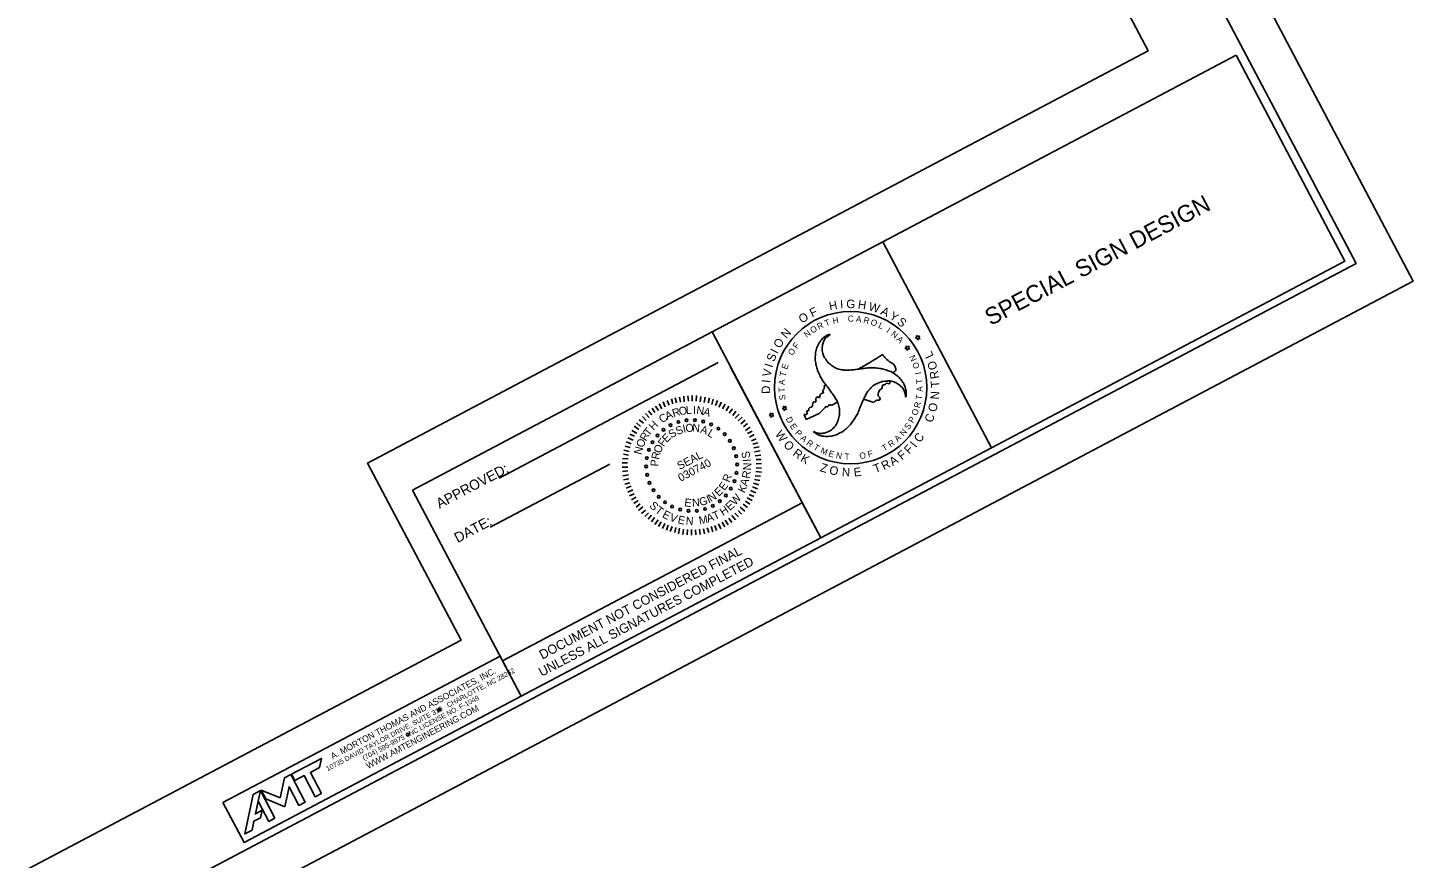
# Model space of a CAD drawing. Extents: x 1789 to 1487599, y -706 to 498569.
# Drawn here: x 2978 to 3796, y -258 to 232 of the extents above; entities that cross this region are included whole.
import ezdxf

# ---------------------------------------------------------------- set-up
doc = ezdxf.new("R2010")
doc.units = 0
for name, color, linetype in [('DEV BORDER CELL', 7, 'Continuous'), ('DEV DOT SWIRL SEAL CELL', 7, 'Continuous'), ('Old_Level_9', 7, 'Continuous'), ('Prop Grid Mask', 7, 'Continuous'), ('Scratch_Level_0', 7, 'Continuous'), ('Sheet Block Title CELL', 7, 'Continuous'), ('Sheet Plot Border Outside CELL', 7, 'Continuous'), ('Sheet Sticker Exception Certification CELL', 7, 'Continuous'), ('Text', 7, 'Continuous')]:
    doc.layers.add(name, color=color, linetype=linetype)

msp = doc.modelspace()

# ---------------------------------------------------------------- linework, layer by layer
at = {"layer": 'DEV BORDER CELL'}
for p, q in [((3255.86, -33.74), (3385.26, 34.59)), ((3392.53, 31.85), (3445.76, -68.96)), ((3250.61, -62.6), (3321.17, -25.35))]:
    msp.add_line(p, q, dxfattribs=at)
for points in [[(3271.54, 1021.61), (1945.09, 321.22), (2435.37, -607.3), (3761.81, 93.1)], [(3691.06, 216.06), (3482.37, 105.86), (3546.58, -15.73), (3755.27, 94.47)], [(3381.56, 52.63), (3482.37, 105.86), (3546.58, -15.73), (3445.76, -68.96)], [(3204.67, -40.77), (3381.56, 52.63), (3445.76, -68.96), (3268.87, -162.36)]]:
    msp.add_lwpolyline(points, close=True, dxfattribs=at)
at = {"layer": 'DEV DOT SWIRL SEAL CELL'}
for p, q in [((3502.53, 49.56), (3501.57, 49.06)), ((3503.13, 49.88), (3502.34, 50.6)), ((3502.34, 50.6), (3502.53, 49.56)), ((3504.09, 50.39), (3503.13, 49.88)), ((3503.61, 49.41), (3504.09, 50.39)), ((3504.38, 48.64), (3503.61, 49.41)), ((3496.44, 43.36), (3495.48, 42.86)), ((3495.48, 42.86), (3496.56, 42.7)), ((3497.05, 43.68), (3496.26, 44.4)), ((3496.26, 44.4), (3496.44, 43.36)), ((3496.56, 42.7), (3496.77, 41.63)), ((3496.77, 41.63), (3497.21, 42.59)), ((3498, 44.19), (3497.05, 43.68)), ((3497.21, 42.59), (3498.29, 42.43)), ((3497.52, 43.21), (3498, 44.19)), ((3498.29, 42.43), (3497.52, 43.21)), ((3501.57, 49.06), (3502.65, 48.9)), ((3502.65, 48.9), (3502.85, 47.83)), ((3502.85, 47.83), (3503.3, 48.79)), ((3503.3, 48.79), (3504.38, 48.64)), ((3424.46, 8.17), (3423.67, 8.89)), ((3423.67, 8.89), (3423.86, 7.85)), ((3425.42, 8.67), (3424.46, 8.17)), ((3424.94, 7.69), (3425.42, 8.67)), ((3451.93, 9.22), (3455.67, 11.16)), ((3471.13, 13.01), (3477.12, 10.89)), ((3416.18, 3.81), (3415.22, 3.3)), ((3415.22, 3.3), (3416.3, 3.15)), ((3416.78, 4.13), (3415.99, 4.85)), ((3415.99, 4.85), (3416.18, 3.81)), ((3416.3, 3.15), (3416.5, 2.07)), ((3416.5, 2.07), (3416.95, 3.04)), ((3417.74, 4.63), (3416.78, 4.13)), ((3416.95, 3.04), (3418.03, 2.88)), ((3416.95, 3.04), (3418.03, 2.88)), ((3417.26, 3.65), (3417.74, 4.63)), ((3417.26, 3.65), (3417.74, 4.63)), ((3418.03, 2.88), (3417.26, 3.65)), ((3418.03, 2.88), (3417.26, 3.65)), ((3423.86, 7.85), (3422.9, 7.34)), ((3422.9, 7.34), (3423.98, 7.19)), ((3423.98, 7.19), (3424.18, 6.11)), ((3424.18, 6.11), (3424.63, 7.08)), ((3424.63, 7.08), (3425.71, 6.92)), ((3425.71, 6.92), (3424.94, 7.69)), ((3437.23, 0.85), (3436.07, 3.24)), ((3444.8, 4.5), (3437.23, 0.85)), ((3448.39, 7.99), (3444.8, 4.5))]:
    msp.add_line(p, q, dxfattribs=at)
for start, end in [(299.03861, 303.15865), (293.51358, 293.81132)]:
    msp.add_arc((3354.62, 234.49), 233.19, start, end, dxfattribs=at)
for points in [[(3441.38, -6.13), (3443.87, -7.09), (3446.44, -7.31), (3448.95, -6.71), (3451.52, -5.54), (3453.75, -3.61), (3454.98, -1.86), (3455.39, -0.92), (3456.11, 0.71), (3456.49, 2.12), (3456.86, 4.99), (3456.69, 8.06), (3455.68, 11.13), (3455.57, 11.38), (3454.15, 14.03), (3452.37, 16.53), (3450.63, 18.91), (3448.74, 21.34), (3446.91, 23.78), (3445.49, 26.34), (3444.09, 29.4), (3443.18, 32.16), (3442.63, 35.21), (3442.43, 36.68), (3442.52, 38.01), (3442.82, 41.17), (3443.84, 44.13), (3444.64, 45.83), (3445.55, 47.16), (3445.7, 47.39), (3447.79, 49.53), (3450.21, 50.93), (3451.15, 51.15)], [(3451.18, 51.26), (3451.15, 51.15), (3449.1, 49.52), (3447.6, 47.36), (3446.86, 44.91), (3446.6, 42.13), (3447.17, 39.21), (3448.04, 37.27), (3448.68, 36.46), (3449.72, 35.01), (3450.73, 33.96), (3453.06, 32.25), (3455.78, 30.83), (3458.98, 30.18), (3459.24, 30.14), (3462.21, 30.03), (3465.3, 30.33), (3468.22, 30.66), (3471.25, 31.08), (3474.29, 31.41), (3477.23, 31.38), (3480.57, 31.08), (3483.4, 30.48), (3486.32, 29.44), (3487.72, 28.87), (3488.81, 28.12), (3491.41, 26.3), (3493.46, 23.92), (3494.55, 22.37), (3495.26, 20.92), (3495.38, 20.69), (3496.15, 17.78), (3496.14, 14.99), (3495.89, 14.09)], [(3488.14, 28.6), (3490.18, 30.03), (3489.6, 31.92), (3488.85, 33.38), (3487.07, 34.58), (3484.1, 36.95), (3482.16, 39.28)], [(3436.07, 3.24), (3435.87, 3.43), (3436.14, 3.89), (3437.48, 4.02), (3437.78, 4.79), (3437.5, 5.25), (3437.7, 5.96), (3438.53, 6.2), (3438.76, 7.41), (3439.29, 7.92), (3440.61, 8.62), (3441.36, 11.02), (3441.95, 11.46), (3442.35, 11.13), (3442.79, 11.27), (3442.81, 12.94), (3442.89, 13.2), (3443.82, 14.33), (3444.28, 14.26), (3444.68, 13.74), (3444.91, 13.73), (3445.17, 14.21), (3445.35, 15.2), (3446.07, 16.26), (3447.3, 16.71), (3446.99, 17.77), (3447.87, 19.38), (3447.86, 20.07), (3447.64, 20.67)], [(3495.89, 14.09), (3495.49, 16.68), (3494.4, 19.04), (3492.61, 20.92), (3490.33, 22.54), (3487.55, 23.5), (3485.43, 23.72), (3484.39, 23.56), (3482.64, 23.43), (3481.18, 23.02), (3478.55, 21.91), (3475.95, 20.23), (3473.81, 17.79), (3473.64, 17.58), (3472.08, 15.03), (3470.78, 12.25), (3469.57, 9.55), (3468.43, 6.7), (3467.22, 3.87), (3465.72, 1.38), (3463.77, -1.38), (3461.84, -3.52), (3459.49, -5.52), (3458.29, -6.46), (3457.1, -7.03), (3454.25, -8.35), (3451.14, -8.96), (3449.28, -9.12), (3447.66, -8.98), (3447.38, -8.97), (3444.49, -8.22), (3442.09, -6.82), (3441.38, -6.13)], [(3477.12, 10.89), (3478.38, 12.13), (3479.88, 12.32), (3480.53, 12.53), (3480.84, 13.17), (3479.69, 14.97), (3479.66, 16.07), (3480.89, 18.63), (3481.99, 19.57), (3482.31, 21.21), (3482.7, 21.38), (3483.45, 21.36), (3484.59, 22.28), (3486.05, 22), (3486.62, 22.36), (3486.61, 23.56)], [(3451.93, 9.22), (3451.32, 9.64), (3450.63, 9.49), (3450.03, 8.63), (3449.42, 8.34), (3448.48, 8.49), (3448.39, 7.99)]]:
    msp.add_spline(points, degree=3, dxfattribs=at)
at = {"layer": 'Old_Level_9'}
for p, q in [((3348.25, 8.74), (3349.98, 6.26)), ((3350.45, 10.19), (3351.97, 7.31)), ((3352.77, 11.41), (3353.96, 8.37)), ((3355.05, 12.19), (3356.23, 9.42)), ((3357.54, 13.09), (3358.39, 10.14)), ((3359.88, 13.75), (3360.5, 10.69)), ((3362.33, 14.2), (3362.95, 11.14)), ((3365, 14.76), (3365.07, 11.41)), ((3367.34, 14.87), (3367.69, 11.8)), ((3369.8, 15.04), (3369.88, 11.68)), ((3372.49, 15.04), (3372.11, 11.73)), ((3375.01, 14.54), (3374.52, 11.45)), ((3377.48, 14.14), (3376.88, 11)), ((3380.01, 13.64), (3379.29, 10.72)), ((3382.32, 13.02), (3381.43, 9.87)), ((3384.8, 12.07), (3383.63, 9.19)), ((3387.17, 11.06), (3385.66, 8.29)), ((3389.32, 9.93), (3387.81, 7.16)), ((3391.53, 8.7), (3389.85, 5.97)), ((3338.47, 0.75), (3341.2, -1.2)), ((3340.44, 2.64), (3342.62, 0.4)), ((3342.19, 4.41), (3344.42, 2.06)), ((3344.06, 5.97), (3346.01, 3.6)), ((3346.2, 7.52), (3347.83, 4.99)), ((3393.68, 7.29), (3391.67, 4.67)), ((3395.56, 5.88), (3393.83, 3.27)), ((3397.67, 4.02), (3395.26, 1.62)), ((3399.44, 2.27), (3397.09, 0.04)), ((3401.1, 0.46), (3398.63, -1.55)), ((3333.01, -7.64), (3335.83, -8.98)), ((3334.14, -5.49), (3337.08, -7.05)), ((3335.53, -3.06), (3338.26, -5.01)), ((3337.06, -1.12), (3339.39, -3.14)), ((3402.54, -1.46), (3400.18, -3.41)), ((3403.99, -3.67), (3401.29, -5.51)), ((3405.33, -5.93), (3402.56, -7.39)), ((3406.43, -8.03), (3403.67, -9.49)), ((3330.26, -14.75), (3333.24, -15.58)), ((3330.93, -12.27), (3333.81, -13.44)), ((3331.94, -9.9), (3334.93, -11.29)), ((3407.55, -10.41), (3404.78, -11.59)), ((3408.55, -12.85), (3405.61, -13.69)), ((3409.33, -15.12), (3406.16, -15.81)), ((3328.8, -22.16), (3331.99, -22.32)), ((3329.25, -19.53), (3332.28, -20.18)), ((3329.53, -17.11), (3332.62, -17.88)), ((3409.89, -17.51), (3406.72, -18.2)), ((3410.39, -20.07), (3406.99, -20.6)), ((3410.67, -22.75), (3407.54, -22.71)), ((3328.52, -24.57), (3331.71, -24.73)), ((3328.52, -27.26), (3331.88, -27.18)), ((3328.69, -29.71), (3331.93, -29.42)), ((3328.91, -32.28), (3332.25, -31.65)), ((3410.22, -32.6), (3407.08, -32.28)), ((3410.73, -30.08), (3407.37, -29.87)), ((3410.79, -27.78), (3407.54, -27.52)), ((3410.78, -25.1), (3407.71, -25.17)), ((3329.36, -34.73), (3332.53, -34.05)), ((3330.03, -37.34), (3333.09, -36.44)), ((3330.81, -39.62), (3333.75, -38.49)), ((3331.81, -42.06), (3334.75, -40.65)), ((3408.32, -39.97), (3405.5, -38.91)), ((3409.11, -37.72), (3406.01, -36.67)), ((3409.72, -35.13), (3406.68, -34.47)), ((3332.81, -44.22), (3335.69, -42.98)), ((3334.04, -46.54), (3336.69, -44.86)), ((3335.32, -48.69), (3338.02, -46.84)), ((3336.7, -50.78), (3339.23, -48.88)), ((3403.82, -49.13), (3401.26, -47.23)), ((3405.23, -46.97), (3402.29, -45.42)), ((3406.24, -44.6), (3403.41, -43.27)), ((3407.48, -42.39), (3404.37, -41.06)), ((3338.2, -52.82), (3340.62, -50.7)), ((3339.98, -54.57), (3342.28, -52.51)), ((3341.86, -56.26), (3344.1, -54.09)), ((3343.91, -58.01), (3345.76, -55.62)), ((3345.79, -59.42), (3347.58, -56.92)), ((3395.36, -58.26), (3393.35, -55.79)), ((3397.17, -56.6), (3395.1, -54.3)), ((3399.03, -55.05), (3396.97, -52.75)), ((3400.84, -53.11), (3398.27, -50.93)), ((3402.47, -51.12), (3399.85, -49.1)), ((3347.89, -60.99), (3349.73, -58.32)), ((3349.93, -62.18), (3351.6, -59.46)), ((3352.42, -63.41), (3353.69, -60.47)), ((3354.68, -64.48), (3355.73, -61.38)), ((3356.93, -65.27), (3358.04, -62.28)), ((3359.52, -65.88), (3360.18, -62.84)), ((3361.82, -66.5), (3362.37, -63.24)), ((3364.35, -67), (3364.78, -63.81)), ((3366.98, -67.17), (3367.14, -63.98)), ((3369.45, -67.28), (3369.43, -64.04)), ((3371.96, -67.22), (3371.89, -64.15)), ((3374.53, -67), (3374.23, -63.76)), ((3377.04, -66.66), (3376.52, -63.54)), ((3379.59, -65.88), (3378.74, -62.94)), ((3381.98, -65.32), (3381.08, -62.27)), ((3384.26, -64.55), (3383.19, -61.72)), ((3386.7, -63.54), (3385.29, -60.61)), ((3389.08, -62.43), (3387.62, -59.66)), ((3391.12, -61.21), (3389.38, -58.45)), ((3393.21, -59.82), (3391.48, -57.34))]:
    msp.add_line(p, q, dxfattribs=at)
for centre in [(3361.69, -0.55), (3366.55, 0.46), (3371.5, 0.56), (3376.39, -0.25), (3349.35, -8.53), (3352.94, -5.12), (3357.1, -2.43), (3381.05, -1.95), (3385.31, -4.48), (3389.04, -7.74), (3344.32, -17.03), (3346.44, -12.55), (3392.11, -11.64), (3394.4, -16.03), (3343.06, -21.82), (3395.86, -20.77), (3342.7, -26.77), (3343.26, -31.69), (3396.05, -30.64), (3396.41, -25.7), (3344.71, -36.43), (3347.01, -40.82), (3392.67, -39.91), (3394.79, -35.43), (3350.07, -44.72), (3353.8, -47.98), (3386.17, -47.34), (3389.76, -43.93), (3358.06, -50.51), (3362.72, -52.21), (3367.61, -53.02), (3372.57, -52.92), (3377.42, -51.91), (3382.01, -50.03)]:
    msp.add_circle(centre, 0.788, dxfattribs=at)
at = {"layer": 'Prop Grid Mask'}
msp.add_lwpolyline([(3092.82, -225.21), (3256.44, -138.82), (3268.87, -162.36), (3105.25, -248.76)], close=True, dxfattribs=at)
at = {"layer": 'Scratch_Level_0'}
msp.add_lwpolyline([(3250.67, 954.05), (2012.65, 300.35), (2456.24, -539.74), (3233.4, -129.38), (3178.18, -24.79), (3639.03, 218.55)], close=True, dxfattribs=at)
at = {"layer": 'Sheet Block Title CELL'}
msp.add_lwpolyline([(3092.82, -225.21), (3256.44, -138.82), (3268.87, -162.36), (3105.25, -248.76)], close=True, dxfattribs=at)
for points in [[(3150.98, -219.86), (3144.4, -207.39), (3149.77, -204.55), (3150.91, -199.21), (3133.31, -208.5), (3135.27, -212.21), (3140.69, -209.35), (3147.27, -221.82), (3150.98, -219.86)], [(3129.29, -227.67), (3131.84, -215.85), (3137.67, -226.89), (3141.38, -224.93), (3132.84, -208.75), (3129.13, -210.71), (3126.52, -222.41), (3115.46, -217.93), (3118.18, -223.08), (3129.29, -227.67)], [(3113.57, -224.49), (3114.98, -218.18), (3110.65, -220.47), (3105.76, -243.74), (3109.96, -241.52), (3111.05, -236.29), (3114.9, -234.26), (3115.92, -229.81), (3111.95, -231.91), (3113.57, -224.49)], [(3123.52, -234.36), (3114.98, -218.18), (3113.57, -224.49), (3119.81, -236.32), (3123.52, -234.36)]]:
    msp.add_lwpolyline(points, dxfattribs=at)
for centre in [(3220.54, -170.43), (3202, -185.14)]:
    msp.add_circle(centre, 0.833, dxfattribs=at)
at = {"layer": 'Sheet Plot Border Outside CELL'}
msp.add_lwpolyline([(2302.9, -705.51), (3795.59, 82.66), (3281.97, 1055.39), (1789.28, 267.21)], close=True, dxfattribs=at)
at = {"layer": 'Sheet Sticker Exception Certification CELL'}
for p, q in [((3257.9, -141.58), (3434.79, -48.18)), ((3434.8, -48.19), (3445.77, -68.97)), ((3445.76, -68.96), (3268.87, -162.36)), ((3268.87, -162.36), (3257.9, -141.58))]:
    msp.add_line(p, q, dxfattribs=at)
at = {"layer": 'Text'}
msp.add_circle((3463.39, 19.74), 44.97, dxfattribs=at)

# ---------------------------------------------------------------- texts
at = {"layer": 'DEV BORDER CELL'}
for s, height, p in [('SPECIAL SIGN DESIGN', 10, (3546.03, 56.07)), ('APPROVED:  ', 6, (3220.65, -51.84)), ('DATE:  ', 6, (3231.35, -72.1))]:
    msp.add_text(s, height=height, rotation=27.83509, dxfattribs=at).set_placement(p)
at = {"layer": 'DEV DOT SWIRL SEAL CELL'}
for s, height, rotation, p in [('F', 5.04, 25.09262, (3440.61, 61.19)), ('H', 5.04, 11.28908, (3451.15, 65.29)), ('I', 5.04, 3.63913, (3457.32, 66.43)), ('G', 5.04, 359.35179, (3460.83, 66.71)), ('H', 5.04, 351.29832, (3467.43, 66.53)), ('W', 5.04, 343.64837, (3473.62, 65.5)), ('A', 5.04, 334.61134, (3480.68, 63.23)), ('O', 5.04, 33.60004, (3434.72, 57.45)), ('R', 3.63, 26.70157, (3444.68, 53.89)), ('H', 3.63, 11.46732, (3453.1, 57.36)), ('C', 3.63, 1.31115, (3461.75, 58.63)), ('A', 3.63, 351.15498, (3466.36, 58.66)), ('R', 3.63, 346.0769, (3470.65, 58.04)), ('O', 3.63, 340.99881, (3474.84, 56.96)), ('L', 3.63, 335.92073, (3479.4, 55.21)), ('Y', 5.04, 327.58347, (3485.87, 60.72)), ('S', 5.04, 321.05999, (3490.38, 57.83)), ('N', 5.04, 49.42115, (3425.5, 48.36)), ('N', 3.63, 36.85774, (3437.52, 48.98)), ('O', 3.63, 31.77966, (3440.85, 51.56)), ('I', 3.63, 325.76456, (3484.2, 52.65)), ('N', 3.63, 320.68647, (3486.9, 50.79)), ('A', 3.63, 315.60839, (3490.21, 47.95)), ('I', 5.04, 62.21591, (3420.08, 39.38)), ('O', 5.04, 57.92857, (3421.67, 42.52)), ('O', 3.63, 57.17008, (3429.08, 38.35)), ('F', 3.63, 52.092, (3431.7, 42.39)), ('I', 5.04, 72.70727, (3417.21, 31.27)), ('S', 5.04, 68.41994, (3418.2, 34.65)), ('E', 3.63, 72.40434, (3425.89, 30.23)), ('N', 3.63, 115.56806, (3502.63, 36.32)), ('O', 3.63, 110.76198, (3504.35, 31.72)), ('V', 5.04, 79.41569, (3416.17, 25.86)), ('T', 3.63, 77.48242, (3424.9, 25.97)), ('I', 3.63, 100.60581, (3505.14, 27.9)), ('T', 3.63, 95.52772, (3505.9, 22.19)), ('D', 5.04, 91.29414, (3415.91, 16.13)), ('I', 5.04, 83.70303, (3415.84, 22.36)), ('T', 3.63, 92.71668, (3424.56, 16.99)), ('A', 3.63, 87.63859, (3424.5, 21.25)), ('A', 3.63, 90.44964, (3505.95, 17.31)), ('S', 3.63, 97.79476, (3425.09, 12.59)), ('R', 3.63, 75.21538, (3504.15, 7.45)), ('T', 3.63, 80.29347, (3505.28, 12.27)), ('D', 3.63, 298.1071, (3424.96, 1.38)), ('P', 3.63, 59.98113, (3500.26, -1.49)), ('O', 3.63, 70.1373, (3502.55, 2.91)), ('E', 3.63, 303.18518, (3427.34, -2.87)), ('P', 3.63, 313.34135, (3430.3, -7.19)), ('N', 3.63, 49.82496, (3494.66, -9.17)), ('S', 3.63, 54.90305, (3497.69, -5.45)), ('A', 3.63, 318.41944, (3433.44, -10.57)), ('R', 3.63, 323.49752, (3436.95, -13.62)), ('T', 3.63, 328.57561, (3441.02, -16.45)), ('M', 3.63, 338.73178, (3445.25, -18.85)), ('T', 3.63, 29.51262, (3483.12, -17.98)), ('R', 3.63, 34.59071, (3486.98, -15.67)), ('A', 3.63, 44.74688, (3491.26, -12.53)), ('E', 3.63, 343.80986, (3449.98, -20.67)), ('N', 3.63, 348.88795, (3454.48, -21.87)), ('T', 3.63, 359.04411, (3459.75, -22.75)), ('O', 3.63, 9.20028, (3468.89, -22.47)), ('F', 3.63, 14.27837, (3473.93, -21.48))]:
    msp.add_text(s, height=height, rotation=rotation, dxfattribs=at).set_placement(p)
at = {"layer": 'Old_Level_9'}
for s, height, rotation, p in [('O', 4.72, 10.92189, (3362.4, 3.35)), ('L', 4.72, 3.581, (3366.24, 4.11)), ('I', 4.72, 358.64105, (3370.26, 4.25)), ('N', 4.72, 352.73893, (3372.11, 4.24)), ('H', 4.72, 45.57844, (3347.06, -5.88)), ('C', 4.72, 32.77501, (3352.05, -1.41)), ('A', 4.72, 25.80995, (3355.14, 0.51)), ('R', 4.72, 17.85665, (3358.9, 2.21)), ('A', 4.72, 344.84016, (3375.98, 3.6)), ('R', 4.72, 60.01054, (3342.61, -12.18)), ('T', 4.72, 53.27087, (3344.45, -9.24)), ('E', 4.7, 44.42402, (3354.77, -12.98)), ('S', 4.7, 32.30312, (3357.62, -10.34)), ('S', 4.7, 20.87655, (3361.09, -8.36)), ('I', 4.7, 13.31716, (3364.86, -6.94)), ('O', 4.7, 5.70998, (3366.09, -6.57)), ('N', 4.7, 355.22811, (3369.71, -6.21)), ('A', 4.7, 341.77886, (3374.26, -6.78)), ('L', 4.7, 329.3674, (3378.48, -8.37)), ('N', 4.72, 75.90175, (3339.88, -20.13)), ('O', 4.72, 67.77931, (3340.86, -16.08)), ('O', 4.7, 66.08691, (3351, -19.49)), ('F', 4.7, 54.23505, (3352.98, -15.48)), ('P', 4.7, 87.95873, (3349.93, -26.84)), ('R', 4.7, 77.58289, (3350.18, -23.03)), ('SEAL', 4.699, 27.83509, (3362.44, -28.95)), ('030740', 4.699, 27.83509, (3363.02, -35.94)), ('S', 4.72, 100.09298, (3404.25, -21.61)), ('I', 4.72, 93.88149, (3404.46, -23.89)), ('R', 4.7, 68.18435, (3391.8, -36.53)), ('R', 4.72, 78.98541, (3403.72, -34.23)), ('N', 4.72, 87.20766, (3404.54, -29.21)), ('E', 4.7, 43.64078, (3385.55, -44.78)), ('E', 4.7, 54.9919, (3389, -41.41)), ('K', 4.72, 63.9761, (3400.64, -42.84)), ('A', 4.72, 71.35678, (3402.22, -38.79)), ('S', 4.72, 316.0471, (3344.18, -50.34)), ('E', 4.7, 352.70428, (3364.99, -50.27)), ('N', 4.7, 3.89345, (3369.91, -50.5)), ('G', 4.7, 15.31634, (3374.71, -50.22)), ('I', 4.7, 23.45968, (3379.54, -48.66)), ('N', 4.7, 30.96288, (3380.87, -47.96)), ('E', 4.72, 41.99985, (3392.09, -53.17)), ('W', 4.72, 49.84085, (3395.36, -50.09)), ('T', 4.72, 323.45948, (3347.55, -53.54)), ('E', 4.72, 331.65758, (3351.76, -56.52)), ('V', 4.72, 339.76489, (3356.12, -58.71)), ('E', 4.72, 348.06633, (3361.04, -60.31)), ('N', 4.72, 356.16408, (3365.92, -61.17)), ('M', 4.72, 10.17213, (3374.21, -61.04)), ('A', 4.72, 18.01726, (3379.11, -59.9)), ('T', 4.72, 25.22168, (3383.2, -58.53)), ('H', 4.72, 33.84631, (3388.08, -56.11))]:
    msp.add_text(s, height=height, rotation=rotation, dxfattribs=at).set_placement(p)
at = {"layer": 'Sheet Block Title CELL'}
for s, height, p in [('A. MORTON THOMAS AND ASSOCIATES, INC.', 3.75, (3157.62, -199.8)), ('10735 DAVID TAYLOR DRIVE, SUITE 310   CHARLOTTE, NC 28262', 2.9167, (3154.63, -206.8)), ('(704) 595-9975   NC LICENSE NO. F-1049', 2.9167, (3176.12, -200.41)), ('WWW.AMTENGINEERING.COM', 3.75, (3178.55, -205.48))]:
    msp.add_text(s, height=height, rotation=27.83461, dxfattribs=at).set_placement(p)
at = {"layer": 'Sheet Sticker Exception Certification CELL'}
for s, p in [('UNLESS ALL SIGNATURES COMPLETED', (3280.99, -151.04)), ('DOCUMENT NOT CONSIDERED FINAL', (3281.36, -140.89))]:
    msp.add_text(s, height=5.5, rotation=27.83509, dxfattribs=at).set_placement(p)
at = {"layer": 'Text'}
for s, height, rotation, p in [('T', 3.63, 21.62349, (3448.88, 55.85)), ('L', 5.04, 115.26408, (3512.56, 38.41)), ('O', 5.04, 106.82474, (3514.77, 30.99)), ('R', 5.04, 100.58696, (3515.68, 25.34)), ('N', 5.04, 86.72707, (3515.5, 12.65)), ('T', 5.04, 94.7161, (3515.98, 19.96)), ('O', 5.04, 78.28773, (3513.9, 5.08)), ('C', 5.04, 70.9158, (3511.6, -1.28)), ('W', 5.04, 305.98508, (3418.55, -7.75)), ('C', 5.04, 55.83839, (3504.47, -13.1)), ('O', 5.04, 314.9498, (3423.38, -14.4)), ('R', 5.04, 323.38915, (3428.83, -19.9)), ('F', 5.04, 45.59775, (3497.98, -19.88)), ('I', 5.04, 51.58536, (3501.92, -16.05)), ('K', 5.04, 329.62693, (3433.34, -23.42)), ('R', 5.04, 26.40074, (3483.03, -29.05)), ('A', 5.04, 32.63852, (3488.21, -26.63)), ('F', 5.04, 39.61015, (3493.66, -23.27)), ('Z', 5.04, 344.00385, (3445, -29.53)), ('O', 5.04, 350.35838, (3450.56, -31.27)), ('N', 5.04, 358.79773, (3458.19, -32.6)), ('E', 5.04, 6.78675, (3465.51, -32.81)), ('T', 5.04, 20.52988, (3477.94, -30.8))]:
    msp.add_text(s, height=height, rotation=rotation, dxfattribs=at).set_placement(p)

doc.saveas('drawing.dxf')
